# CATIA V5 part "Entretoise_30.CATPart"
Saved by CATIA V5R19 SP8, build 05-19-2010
Part number: Entretoise_30
Bounding box of the stored display mesh (mm): x -19 to 19, y -18.807 to 18.807, z 0 to 40
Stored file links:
  G:\EU_thinkMotion\CFAO_2010\MMS_groupe1\MMS_groupe1\OK\vduret\vduret\CATIA\Entretoise_30.CATPart
  F:\CFAO TP\Machine_de_coupe.CATProduct
  G:\EU_thinkMotion\CFAO_2010\MMS_groupe1\MMS_groupe1\OK\vduret\vduret\CATIA\Disque_porteur.CATPart
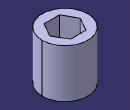
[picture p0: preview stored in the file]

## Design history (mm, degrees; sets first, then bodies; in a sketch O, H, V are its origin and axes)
Body1 (main body)
  Sketch1 on xy-plane, origin (0, 0, 0), H (1, 0, 0), V (0, 1, 0)
    circle A1 centre (0, 0) radius 19
    point P1 (0, 0)
    point P2 (6.3509, -11)
    point P3 (12.7017, 0)
    point P4 (6.3509, 11)
    point P5 (-6.3509, 11)
    point P6 (-12.7017, 0)
    point P7 (-6.3509, -11)
    point P8 (9.5263, -5.5)
    line L1 (6.3509, -11) -> (12.7017, 0)
    line L2 (12.7017, 0) -> (6.3509, 11)
    line L3 (6.3509, 11) -> (-6.3509, 11)
    line L4 (-6.3509, 11) -> (-12.7017, 0)
    line L5 (-12.7017, 0) -> (-6.3509, -11)
    line L6 (-6.3509, -11) -> (6.3509, -11)
    construction line L7 (0, 0) -> (9.5263, -5.5)
    construction circle A2 centre (0, 0) radius 12.7017
    construction arc A3 centre (-12.7017, 0) radius 12.7017 from (-6.3509, 11) to (-6.3509, -11) cw
    construction arc A4 centre (12.7017, 0) radius 12.7017 from (6.3509, 11) to (6.3509, -11) ccw
    radius A1 = 19
    distance L3 L6 = 22
    coincidence: A2 P2, A2 P3, A2 P4, A2 P5, A2 P6, A2 P7, A3 P1, A4 P1, O P1
    midpoint: P8 L1
    parallelism: L1 L4
    horizontal: L3 H
  Pad1: profile Sketch1, direction (0, 0, 1), length 40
